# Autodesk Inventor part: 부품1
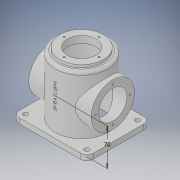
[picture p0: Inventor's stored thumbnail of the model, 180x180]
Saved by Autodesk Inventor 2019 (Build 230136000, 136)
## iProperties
Created: 2020-12
Part Number: 부품1
Material: 일반
Document SubType Name: Modeling
Designer: jun-1-15
Density: 1 g/cm^3
Appearance: 기본값
Author: jun-1-15
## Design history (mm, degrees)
sketch "스케치1"
  geometry: C1 r 50 at (0, 0); 1 further point
  constraints: 1 centre point, 1 coincident
  dimensions: "d0" = 100 diameter of C1
extrude "돌출1" new body sketch "스케치1" distance "d1" = 120; taper "d2" = 0 deg
sketch "스케치2"
  geometry: L1 (70, -60)-(-70, -60); L2 (-70, -60)-(-70, 60); L3 (-70, 60)-(70, 60); L4 (70, 60)-(70, -60); L5 (70, -60)-(-70, 60); L6 (-70, -60)-(70, 60); C1 r 50 at (0, 0) reference; 1 further point
  constraints: 12 end point, 2 midpoint, 2 parallel, 1 horizontal, 1 perpendicular
  dimensions: "d3" = 140 distance of L2.end L3.end; "d4" = 120 distance of L1.end L2.end
extrude "돌출2" join sketch "스케치2" distance "d5" = 10; taper "d6" = 0 deg
sketch "스케치3"
  geometry: C1 r 41 at (0, 0); 1 further point
  constraints: 1 centre point, 1 coincident
  dimensions: "d7" = 82 diameter of C1
extrude "돌출3" join sketch "스케치3" distance "d8" = 5; taper "d9" = 0 deg
sketch "스케치4"
  geometry: 2 further points
  constraints: 1 coincident
hole "구멍1" sketch "스케치4" at (0, 0) diameter "d10" = 54; stored, may be unused: countersink angle "d14" = 90 deg, drill point angle "d16" = 0 deg; dims "d11" = 18, "d12" = 84, "d13" = 112, "d15" = 13
node "작업 평면1"
sketch "스케치5"
  geometry: L1 (0, -60)-(0, 60) reference; C1 r 41 at (60, 0); 2 further points
  constraints: 1 centre point, 1 horizontal alignment, 1 midpoint
  dimensions: "d18" = 82 diameter of C1; "d19" = 60 distance from line of L1 C1.centre
extrude "돌출4" join sketch "스케치5" stored distance "d20" = 15; taper "d21" = 0 deg
sketch "스케치7"
  geometry: C1 r 41 at (0, 0) reference; 2 further points
  constraints: 1 vertical alignment
  dimensions: "d29" = 33 distance of C1.centre point (0, 33)
hole "구멍3" sketch "스케치7" at (0, 33) diameter "d30" = 3.242; stored, may be unused: countersink angle "d34" = 90 deg, drill point angle "d36" = 118 deg; dims "d31" = 8, "d32" = 4, "d33" = 2, "d35" = 12
sketch "스케치8"
  geometry: C1 r 41 at (0, 0) reference; 2 further points
  constraints: 1 coincident
hole "구멍4" sketch "스케치8" at (0, 0) diameter "d40" = 54; stored, may be unused: countersink angle "d44" = 90 deg, drill point angle "d46" = 0 deg; dims "d41" = 8, "d42" = 4, "d43" = 2, "d45" = 12
fillet "모깎기1" dims "d47" = 12
sketch "스케치9"
  geometry: 2 further points
  constraints: 1 vertical alignment
  dimensions: "d48" = 33 distance of point (0, 0) point (0, 33)
hole "구멍5" sketch "스케치9" at (0, 33) diameter "d49" = 3.242; stored, may be unused: countersink angle "d53" = 90 deg, drill point angle "d55" = 118 deg; dims "d50" = 8, "d51" = 4, "d52" = 2, "d54" = 10
fillet "모깎기2" dims "d59" = 6
sketch "스케치10"
  geometry: A1 r 12 centre (-58, -48) between (-70, -48) and (-58, -60) reference; 2 further points
  constraints: 1 coincident
hole "구멍6" sketch "스케치10" at (-58, -48) diameter "d60" = 9; stored, may be unused: countersink angle "d64" = 90 deg, drill point angle "d66" = 118 deg; dims "d61" = 8, "d62" = 4, "d63" = 2, "d65" = 10
node "작업 평면3"
sketch "스케치11"
  geometry: L1 (58, 0)-(-58, 0) reference; 3 further points
  constraints: 1 midpoint, 1 vertical alignment, 1 other
  dimensions: "d67" = 70 distance from line of L1 point (0, 70)
node "솔리드1"
pattern_circular "원형 패턴1" dims angle "d38" = 360 deg
mirror "미러1"
pattern_circular "원형 패턴2" dims angle "d57" = 360 deg
mirror "미러2"
mirror "미러3"
node "투영된 루프1"
node "투영된 루프2"
other parameters: "d17" = 59
